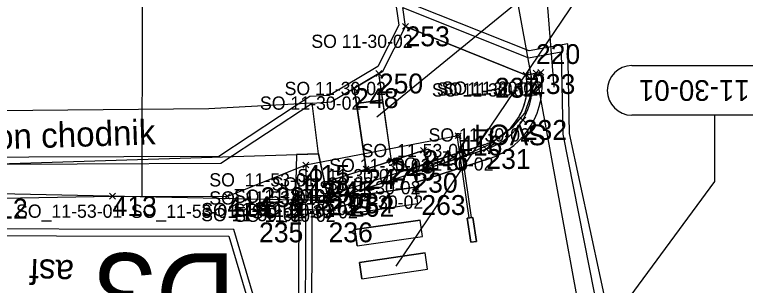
# Model space of a CAD drawing. Extents: x -728800 to -728100, y -1073200 to -1072700.
# Drawn here: x -728528.71 to -728506.62, y -1073027.29 to -1073019.12 of the extents above; entities that cross this region are included whole.
import ezdxf

# ---------------------------------------------------------------- set-up
doc = ezdxf.new("R2010")
doc.units = 0
for name, color, linetype in [('_NOR-návrh tenká', 7, 'Continuous'), ('_NOR-návrh tenká obec', 7, 'Continuous'), ('_NOR-VDZ', 7, 'Continuous'), ('_NOR-šraf_+12', 7, 'Continuous'), ('_NOR-šraf_chodník', 7, 'Continuous'), ('_NOR-šraf_signální pás', 7, 'Continuous'), ('_NOR-šraf_varovný pás', 7, 'Continuous'), ('_NOR-šraf_vozovka', 7, 'Continuous'), ('_NOR-šraf_zeleň', 7, 'Continuous'), ('A2_OBVOD STAVBY', 7, 'Continuous'), ('B1_body_poloha', 7, 'Continuous'), ('B2_body_číslo', 7, 'Continuous'), ('B3_body_popiska', 7, 'Continuous'), ('B6_JŽM', 7, 'Continuous'), ('KOS_kabelová trasa VO', 7, 'Continuous'), ('KOS_nové prvky VO', 7, 'Continuous'), ('KTA_členění PS a SO', 7, 'Continuous'), ('ZA_02_Dočasný_do_1_roku', 7, 'Continuous')]:
    doc.layers.add(name, color=color, linetype=linetype)

msp = doc.modelspace()

# ---------------------------------------------------------------- linework, layer by layer
at = {"layer": '_NOR-návrh tenká'}
msp.add_line((-728515.702, -1073023.588), (-728515.748, -1073023.445), dxfattribs=at)
at = {"layer": '_NOR-návrh tenká obec'}
for p, q in [((-728513.244, -1073020.944), (-728516.889, -1073019.476)), ((-728517.313, -1073023.532), (-728517.697, -1073020.9)), ((-728513.096, -1073020.917), (-728513.244, -1073020.944)), ((-728518.085, -1073023.782), (-728518.441, -1073021.342)), ((-728516.347, -1073023.219), (-728516.224, -1073023.599)), ((-728516.7, -1073023.753), (-728515.725, -1073023.516)), ((-728515.725, -1073023.516), (-728516.653, -1073023.896)), ((-728516.653, -1073023.896), (-728516.7, -1073023.753)), ((-728519.228, -1073024.153), (-728519.105, -1073024.534)), ((-728518.629, -1073024.379), (-728519.235, -1073024.653)), ((-728518.583, -1073024.522), (-728518.629, -1073024.379)), ((-728518.569, -1073024.622), (-728516.59, -1073024.333)), ((-728516.517, -1073024.828), (-728516.59, -1073024.333)), ((-728520.218, -1073024.707), (-728520.215, -1073024.557)), ((-728519.235, -1073024.653), (-728518.583, -1073024.522)), ((-728518.496, -1073025.117), (-728518.569, -1073024.622)), ((-728518.496, -1073025.117), (-728516.517, -1073024.828)), ((-728518.424, -1073025.611), (-728516.445, -1073025.322)), ((-728516.373, -1073025.817), (-728516.445, -1073025.322)), ((-728518.352, -1073026.106), (-728518.424, -1073025.611)), ((-728518.352, -1073026.106), (-728516.373, -1073025.817)), ((-728518.28, -1073026.601), (-728516.301, -1073026.312)), ((-728516.228, -1073026.807), (-728516.301, -1073026.312)), ((-728518.207, -1073027.096), (-728518.28, -1073026.601)), ((-728518.207, -1073027.096), (-728516.228, -1073026.807))]:
    msp.add_line(p, q, dxfattribs=at)
for points in [[(-728512.801, -1073020.863), (-728513.096, -1073020.917)], [(-728516.7, -1073023.753), (-728514.493, -1073023.037)], [(-728519.228, -1073024.153), (-728516.347, -1073023.219)], [(-728516.653, -1073023.896), (-728514.446, -1073023.18)], [(-728516.653, -1073023.896), (-728516.561, -1073024.181), (-728514.354, -1073023.465)], [(-728518.629, -1073024.379), (-728516.7, -1073023.753)], [(-728518.583, -1073024.522), (-728516.653, -1073023.896)], [(-728520.215, -1073024.557), (-728519.24, -1073024.577), (-728518.629, -1073024.379)], [(-728520.218, -1073024.707), (-728520.224, -1073025.007), (-728519.174, -1073025.029), (-728518.491, -1073024.807), (-728518.491, -1073024.807), (-728518.583, -1073024.522)], [(-728520.218, -1073024.707), (-728519.218, -1073024.728), (-728518.583, -1073024.522)]]:
    msp.add_lwpolyline(points, dxfattribs=at)
for radius in [2.3, 1.85, 2]:
    msp.add_arc((-728515.063, -1073021.278), radius, 287.972, 10.3872, dxfattribs=at)
at = {"layer": '_NOR-VDZ'}
for p, q in [((-728518.569, -1073024.622), (-728516.59, -1073024.333)), ((-728516.517, -1073024.828), (-728516.59, -1073024.333)), ((-728518.496, -1073025.117), (-728518.569, -1073024.622)), ((-728518.496, -1073025.117), (-728516.517, -1073024.828)), ((-728518.424, -1073025.611), (-728516.445, -1073025.322)), ((-728516.373, -1073025.817), (-728516.445, -1073025.322)), ((-728518.352, -1073026.106), (-728518.424, -1073025.611)), ((-728518.352, -1073026.106), (-728516.373, -1073025.817)), ((-728518.28, -1073026.601), (-728516.301, -1073026.312)), ((-728516.228, -1073026.807), (-728516.301, -1073026.312)), ((-728518.207, -1073027.096), (-728518.28, -1073026.601)), ((-728518.207, -1073027.096), (-728516.228, -1073026.807))]:
    msp.add_line(p, q, dxfattribs=at)
for points in [[(-728512.949, -1073020.89), (-728510.942, -1073031.839)], [(-728518.496, -1073025.117), (-728516.517, -1073024.828), (-728516.59, -1073024.333), (-728518.569, -1073024.622), (-728518.496, -1073025.117), (-728518.496, -1073025.117)], [(-728518.352, -1073026.106), (-728516.373, -1073025.817), (-728516.445, -1073025.322), (-728518.424, -1073025.611), (-728518.352, -1073026.106), (-728518.352, -1073026.106)], [(-728518.207, -1073027.096), (-728516.228, -1073026.807), (-728516.301, -1073026.312), (-728518.28, -1073026.601), (-728518.207, -1073027.096), (-728518.207, -1073027.096)]]:
    msp.add_lwpolyline(points, dxfattribs=at)
at = {"layer": '_NOR-šraf_+12'}
for points in [[(-728513.244, -1073020.944), (-728513.096, -1073020.917)], [(-728515.748, -1073023.445), (-728514.493, -1073023.037)], [(-728514.446, -1073023.18), (-728515.702, -1073023.588), (-728515.725, -1073023.516), (-728515.748, -1073023.445), (-728515.748, -1073023.445)], [(-728520.218, -1073024.707), (-728520.215, -1073024.557), (-728519.251, -1073024.577), (-728519.235, -1073024.653), (-728519.218, -1073024.728), (-728520.218, -1073024.707)]]:
    msp.add_lwpolyline(points, dxfattribs=at)
for radius in [1.85, 2]:
    msp.add_arc((-728515.063, -1073021.278), radius, 287.972, 10.3872, dxfattribs=at)
at = {"layer": '_NOR-šraf_chodník'}
msp.add_line((-728513.793, -1073022.623), (-728514.141, -1073022.881), dxfattribs=at)
for points in [[(-728517.313, -1073023.532), (-728517.697, -1073020.9), (-728517.575, -1073020.827), (-728516.889, -1073019.476), (-728513.244, -1073020.944)], [(-728519.526, -1073023.322), (-728519.714, -1073021.793), (-728519.139, -1073021.757), (-728518.441, -1073021.342), (-728518.085, -1073023.782), (-728519.228, -1073024.153), (-728519.105, -1073024.534), (-728519.24, -1073024.577), (-728519.251, -1073024.577), (-728519.526, -1073023.322)], [(-728514.493, -1073023.037), (-728515.748, -1073023.445), (-728516.224, -1073023.599), (-728516.347, -1073023.219), (-728517.313, -1073023.532)]]:
    msp.add_lwpolyline(points, dxfattribs=at)
for start, end in [(313.3529, 10.3872), (287.972, 299.9219)]:
    msp.add_arc((-728515.063, -1073021.278), 1.85, start, end, dxfattribs=at)
at = {"layer": '_NOR-šraf_signální pás'}
for points in [[(-728518.373, -1073021.807), (-728517.581, -1073021.696), (-728517.697, -1073020.9), (-728518.441, -1073021.342), (-728518.373, -1073021.807)], [(-728517.581, -1073021.696), (-728518.373, -1073021.807), (-728518.085, -1073023.782), (-728517.313, -1073023.532), (-728517.581, -1073021.696)]]:
    msp.add_lwpolyline(points, dxfattribs=at)
at = {"layer": '_NOR-šraf_varovný pás'}
msp.add_lwpolyline([(-728518.629, -1073024.379), (-728516.7, -1073023.753), (-728516.224, -1073023.599), (-728516.347, -1073023.219), (-728517.313, -1073023.532), (-728518.085, -1073023.782), (-728519.228, -1073024.153), (-728519.105, -1073024.534), (-728518.629, -1073024.379)], dxfattribs=at)
at = {"layer": '_NOR-šraf_vozovka'}
for points in [[(-728513.096, -1073020.917), (-728512.801, -1073020.863)], [(-728516.653, -1073023.896), (-728515.702, -1073023.588), (-728514.446, -1073023.18)], [(-728514.354, -1073023.465), (-728516.561, -1073024.181), (-728516.653, -1073023.896)], [(-728518.583, -1073024.522), (-728518.539, -1073024.823), (-728519.174, -1073025.029), (-728520.224, -1073025.007), (-728520.218, -1073024.707), (-728519.218, -1073024.728), (-728518.583, -1073024.522)], [(-728518.539, -1073024.823), (-728518.583, -1073024.522), (-728518.491, -1073024.807), (-728518.539, -1073024.823)]]:
    msp.add_lwpolyline(points, dxfattribs=at)
for radius in [2.3, 2]:
    msp.add_arc((-728515.063, -1073021.278), radius, 287.972, 10.3872, dxfattribs=at)
at = {"layer": '_NOR-šraf_zeleň'}
msp.add_lwpolyline([(-728520.215, -1073024.557), (-728519.251, -1073024.577), (-728519.526, -1073023.322), (-728520.189, -1073023.343), (-728520.215, -1073024.557)], dxfattribs=at)
at = {"layer": 'A2_OBVOD STAVBY'}
for points in [[(-728564.164, -1073015.523), (-728556.425, -1073019.431), (-728548.14, -1073022.833), (-728542.882, -1073024.621), (-728538.694, -1073025.349), (-728534.14, -1073025.737), (-728532.664, -1073025.787), (-728522.232, -1073025.806), (-728521.488, -1073028.32), (-728521.545, -1073030.726), (-728521.594, -1073032.788), (-728517.755, -1073032.879), (-728517.209, -1073045.129)], [(-728509.455, -1073035.234), (-728510.689, -1073028.502), (-728511.933, -1073022.707), (-728511.986, -1073020.002), (-728513.157, -1073020.217), (-728515.255, -1073019.379), (-728517.216, -1073018.59), (-728517.096, -1073019.442), (-728517.727, -1073020.685), (-728519.2, -1073021.56), (-728519.78, -1073021.597), (-728522.531, -1073023.408), (-728531.159, -1073023.437), (-728533.997, -1073023.341), (-728538.386, -1073022.967), (-728542.291, -1073022.287), (-728547.296, -1073020.586), (-728553.966, -1073017.86)]]:
    msp.add_lwpolyline(points, dxfattribs=at)
at = {"layer": 'B1_body_poloha'}
for p, q in [((-728516.977, -1073019.388), (-728516.801, -1073019.564)), ((-728516.977, -1073019.564), (-728516.801, -1073019.388)), ((-728517.785, -1073020.812), (-728517.609, -1073020.988)), ((-728517.785, -1073020.988), (-728517.609, -1073020.812)), ((-728513.332, -1073020.856), (-728513.156, -1073021.032)), ((-728513.332, -1073021.032), (-728513.156, -1073020.856)), ((-728513.037, -1073020.802), (-728512.861, -1073020.978)), ((-728513.037, -1073020.978), (-728512.861, -1073020.802)), ((-728512.889, -1073020.775), (-728512.713, -1073020.951)), ((-728512.889, -1073020.951), (-728512.713, -1073020.775)), ((-728518.529, -1073021.254), (-728518.353, -1073021.43)), ((-728518.529, -1073021.43), (-728518.353, -1073021.254)), ((-728513.434, -1073022.214), (-728513.257, -1073022.391)), ((-728513.434, -1073022.391), (-728513.257, -1073022.214)), ((-728515.389, -1073022.686), (-728515.213, -1073022.862)), ((-728515.389, -1073022.862), (-728515.213, -1073022.686)), ((-728514.534, -1073023.092), (-728514.358, -1073023.268)), ((-728514.534, -1073023.268), (-728514.358, -1073023.092)), ((-728516.435, -1073023.131), (-728516.259, -1073023.307)), ((-728516.435, -1073023.307), (-728516.259, -1073023.131)), ((-728517.401, -1073023.444), (-728517.225, -1073023.62)), ((-728517.401, -1073023.62), (-728517.225, -1073023.444)), ((-728519.993, -1073023.571), (-728519.817, -1073023.747)), ((-728519.993, -1073023.747), (-728519.817, -1073023.571)), ((-728518.173, -1073023.694), (-728517.997, -1073023.87)), ((-728518.173, -1073023.87), (-728517.997, -1073023.694)), ((-728516.742, -1073023.808), (-728516.565, -1073023.984)), ((-728516.742, -1073023.984), (-728516.565, -1073023.808)), ((-728519.995, -1073024.117), (-728519.819, -1073024.293)), ((-728519.995, -1073024.293), (-728519.819, -1073024.117)), ((-728516.678, -1073024.245), (-728516.502, -1073024.421)), ((-728516.678, -1073024.421), (-728516.502, -1073024.245)), ((-728525.835, -1073024.516), (-728525.659, -1073024.692)), ((-728525.835, -1073024.692), (-728525.659, -1073024.516)), ((-728522.365, -1073024.519), (-728522.189, -1073024.695)), ((-728522.365, -1073024.695), (-728522.189, -1073024.519)), ((-728520.306, -1073024.618), (-728520.129, -1073024.795)), ((-728520.306, -1073024.795), (-728520.129, -1073024.618)), ((-728520.303, -1073024.469), (-728520.127, -1073024.645)), ((-728520.303, -1073024.645), (-728520.127, -1073024.469)), ((-728519.323, -1073024.564), (-728519.146, -1073024.741)), ((-728519.323, -1073024.741), (-728519.146, -1073024.564)), ((-728518.671, -1073024.434), (-728518.495, -1073024.61)), ((-728518.671, -1073024.61), (-728518.495, -1073024.434))]:
    msp.add_line(p, q, dxfattribs=at)
at = {"layer": 'B2_body_číslo'}
for p, q in [((-728516.889, -1073019.476), (-728516.889, -1073019.476)), ((-728512.949, -1073020.89), (-728512.949, -1073020.89)), ((-728517.697, -1073020.9), (-728517.697, -1073020.9)), ((-728513.244, -1073020.944), (-728513.244, -1073020.944)), ((-728513.096, -1073020.917), (-728513.096, -1073020.917)), ((-728518.441, -1073021.342), (-728518.441, -1073021.342)), ((-728513.346, -1073022.302), (-728513.346, -1073022.302)), ((-728515.301, -1073022.774), (-728515.301, -1073022.774)), ((-728516.347, -1073023.219), (-728516.347, -1073023.219)), ((-728514.446, -1073023.18), (-728514.446, -1073023.18)), ((-728517.313, -1073023.532), (-728517.313, -1073023.532)), ((-728519.905, -1073023.659), (-728519.905, -1073023.659)), ((-728518.085, -1073023.782), (-728518.085, -1073023.782)), ((-728516.653, -1073023.896), (-728516.653, -1073023.896)), ((-728519.907, -1073024.205), (-728519.907, -1073024.205)), ((-728519.228, -1073024.153), (-728519.228, -1073024.153)), ((-728516.59, -1073024.333), (-728516.59, -1073024.333)), ((-728525.747, -1073024.604), (-728525.747, -1073024.604)), ((-728522.277, -1073024.607), (-728522.277, -1073024.607)), ((-728520.215, -1073024.557), (-728520.215, -1073024.557)), ((-728519.24, -1073024.577), (-728519.24, -1073024.577)), ((-728518.583, -1073024.522), (-728518.583, -1073024.522)), ((-728518.569, -1073024.622), (-728518.569, -1073024.622)), ((-728520.218, -1073024.707), (-728520.218, -1073024.707)), ((-728519.218, -1073024.728), (-728519.218, -1073024.728)), ((-728515.024, -1073025.266), (-728515.024, -1073025.266)), ((-728514.856, -1073025.241), (-728514.856, -1073025.241)), ((-728514.749, -1073025.969), (-728514.749, -1073025.969)), ((-728514.917, -1073025.994), (-728514.917, -1073025.994))]:
    msp.add_line(p, q, dxfattribs=at)
at = {"layer": 'B6_JŽM'}
for p, q in [((-728522.835, -1073021.968), (-728542.221, -1073022.127)), ((-728519.526, -1073023.322), (-728519.218, -1073024.728))]:
    msp.add_line(p, q, dxfattribs=at)
for points in [[(-728512.398, -1073021.312), (-728513.144, -1073011.93), (-728518.016, -1072994.823)], [(-728535.414, -1073024.787), (-728529.18, -1073024.517), (-728519.218, -1073024.728), (-728515.346, -1073023.472), (-728514.359, -1073023.043), (-728513.624, -1073022.497), (-728513.279, -1073022.092), (-728513.109, -1073021.591), (-728513.091, -1073020.945), (-728514.696, -1073012.189)], [(-728532.088, -1073023.721), (-728519.526, -1073023.322), (-728519.714, -1073021.793), (-728522.835, -1073021.968)]]:
    msp.add_lwpolyline(points, dxfattribs=at)
at = {"layer": 'KOS_kabelová trasa VO'}
for p, q in [((-728520.126, -1073029.729), (-728520.105, -1073024.204)), ((-728519.726, -1073029.73), (-728519.705, -1073024.205))]:
    msp.add_line(p, q, dxfattribs=at)
for points in [[(-728561.457, -1073013.169), (-728562.506, -1073015.027), (-728558.898, -1073016.89), (-728555.929, -1073018.337), (-728552.96, -1073019.584), (-728550.284, -1073020.683), (-728547.718, -1073021.71), (-728545.504, -1073022.477), (-728542.587, -1073023.454), (-728538.54, -1073024.158), (-728535.432, -1073024.48), (-728532.705, -1073024.598), (-728529.651, -1073024.677), (-728525.747, -1073024.604), (-728522.277, -1073024.607), (-728519.905, -1073023.659), (-728515.301, -1073022.774)], [(-728519.905, -1073023.659), (-728519.931, -1073030.624), (-728519.35, -1073030.638), (-728519.331, -1073029.784)]]:
    msp.add_lwpolyline(points, dxfattribs=at)
at = {"layer": 'KOS_nové prvky VO'}
for p, q in [((-728515.331, -1073022.834), (-728514.978, -1073025.253)), ((-728515.256, -1073022.823), (-728514.902, -1073025.242))]:
    msp.add_line(p, q, dxfattribs=at)
msp.add_lwpolyline([(-728514.917, -1073025.994), (-728515.024, -1073025.266), (-728514.856, -1073025.241), (-728514.749, -1073025.969)], close=True, dxfattribs=at)
msp.add_lwpolyline([(-728514.749, -1073025.969), (-728514.856, -1073025.241), (-728515.024, -1073025.266), (-728514.917, -1073025.994), (-728514.749, -1073025.969)], dxfattribs=at)
msp.add_circle((-728515.301, -1073022.774), 0.0665, dxfattribs=at)
at = {"layer": 'KTA_členění PS a SO'}
for p, q in [((-728509.672, -1073015.622), (-728517.759, -1073022.219)), ((-728509.672, -1073015.622), (-728517.188, -1073026.72)), ((-728524.851, -1073017.78), (-728524.858, -1073024.605)), ((-728507.548, -1073022.158), (-728507.548, -1073024.158)), ((-728507.548, -1073024.158), (-728512.902, -1073031.401))]:
    msp.add_line(p, q, dxfattribs=at)
for points in [[(-728510.048, -1073020.658), (-728505.048, -1073020.658)], [(-728505.048, -1073022.158), (-728510.048, -1073022.158)]]:
    msp.add_lwpolyline(points, dxfattribs=at)
msp.add_arc((-728510.042, -1073021.408), 0.75, 90.4529, 269.5471, dxfattribs=at)
at = {"layer": 'ZA_02_Dočasný_do_1_roku'}
for points in [[(-728542.341, -1073022.482), (-728538.412, -1073023.165), (-728534.009, -1073023.54), (-728531.162, -1073023.637), (-728526.817, -1073023.623), (-728522.471, -1073023.608), (-728519.714, -1073021.793), (-728519.139, -1073021.757), (-728517.575, -1073020.827), (-728516.889, -1073019.476), (-728516.969, -1073018.905), (-728513.177, -1073020.424), (-728512.181, -1073020.241), (-728512.132, -1073022.73), (-728509.606, -1073035.517), (-728510.327, -1073035.465), (-728509.415, -1073042.185)], [(-728517.01, -1073045.12), (-728517.286, -1073038.902), (-728517.563, -1073032.683), (-728521.389, -1073032.592), (-728521.287, -1073028.294), (-728522.083, -1073025.607), (-728532.66, -1073025.587), (-728536.398, -1073025.344), (-728538.668, -1073025.15), (-728542.832, -1073024.426)]]:
    msp.add_lwpolyline(points, dxfattribs=at)

# ---------------------------------------------------------------- texts
at = {"layer": 'B2_body_číslo'}
for s, p in [('253', (-728516.889, -1073020.076)), ('220', (-728512.949, -1073020.612)), ('250', (-728517.697, -1073021.5)), ('237', (-728514.189, -1073021.628)), ('233', (-728513.096, -1073021.517)), ('248', (-728518.441, -1073021.942)), ('232', (-728513.346, -1073022.902)), ('416', (-728515.301, -1073023.374)), ('246', (-728516.347, -1073023.819)), ('231', (-728514.446, -1073023.78)), ('249', (-728517.313, -1073024.132)), ('415', (-728519.905, -1073024.259)), ('247', (-728518.085, -1073024.382)), ('230', (-728516.653, -1073024.496)), ('429', (-728519.907, -1073024.805)), ('245', (-728519.228, -1073024.753)), ('238', (-728521.273, -1073024.933)), ('413', (-728525.747, -1073025.204)), ('414', (-728522.277, -1073025.207)), ('239', (-728519.24, -1073025.177)), ('234', (-728518.583, -1073025.122)), ('262', (-728518.569, -1073025.222)), ('263', (-728516.413, -1073025.169)), ('412', (-728529.651, -1073025.277)), ('235', (-728521.319, -1073025.995)), ('236', (-728519.218, -1073025.994))]:
    msp.add_text(s, height=0.6, dxfattribs=at).set_placement(p)
at = {"layer": 'B3_body_popiska'}
for s, p in [('SO 11-30-02', (-728519.738, -1073020.126)), ('SO 11-30-02', (-728520.546, -1073021.55)), ('SO 11-30-02', (-728516.093, -1073021.594)), ('SO 11-30-02', (-728515.945, -1073021.567)), ('SO 11-30-02', (-728515.798, -1073021.54)), ('SO 11-30-02', (-728521.29, -1073021.992)), ('SO 11-30-02', (-728516.195, -1073022.952)), ('SO_11-53-01', (-728518.217, -1073023.424)), ('SO 11-30-02', (-728519.196, -1073023.869)), ('SO 11-30-02', (-728517.295, -1073023.83)), ('SO_11-53-01', (-728522.821, -1073024.309)), ('SO 11-30-02', (-728520.162, -1073024.182)), ('SO 11-30-02', (-728520.934, -1073024.432)), ('SO 11-30-02', (-728519.502, -1073024.546)), ('SO 11-30-02', (-728522.077, -1073024.803)), ('SO_11-53-01', (-728522.823, -1073024.855)), ('SO_11-30-02', (-728519.566, -1073024.983)), ('SO_11-53-01', (-728528.663, -1073025.254)), ('SO_11-53-01', (-728525.193, -1073025.257)), ('SO 11-30-02', (-728523.064, -1073025.207)), ('SO 11-30-02', (-728522.089, -1073025.227)), ('SO_11-30-02', (-728521.545, -1073025.272)), ('SO 11-30-02', (-728521.432, -1073025.172)), ('SO 11-30-02', (-728523.067, -1073025.357)), ('SO 11-30-02', (-728522.067, -1073025.378))]:
    msp.add_text(s, height=0.4, dxfattribs=at).set_placement(p)
at = {"layer": 'B6_JŽM'}
for s, rotation, p in [('beton chodnik', 1.8192, (-728530.683, -1073023.234)), ('asf', 178.1898, (-728526.904, -1073026.538))]:
    msp.add_text(s, height=0.75, rotation=rotation, dxfattribs=at).set_placement(p)
at = {"layer": 'KOS_nové prvky VO'}
msp.add_text('SVO4', height=0.625, rotation=180, dxfattribs=at).set_placement((-728512.622, -1073022.439))
at = {"layer": 'KTA_členění PS a SO'}
msp.add_text('SO 11-30-01', height=0.625, rotation=180, dxfattribs=at).set_placement((-728505.049, -1073021.099))
at = {"layer": 'ZA_02_Dočasný_do_1_roku'}
msp.add_text('D3', height=2.5, rotation=180, dxfattribs=at).set_placement((-728522.024, -1073026.326))

doc.saveas('drawing.dxf')
